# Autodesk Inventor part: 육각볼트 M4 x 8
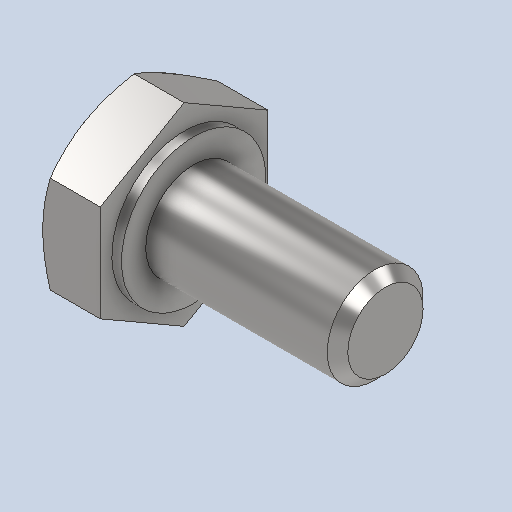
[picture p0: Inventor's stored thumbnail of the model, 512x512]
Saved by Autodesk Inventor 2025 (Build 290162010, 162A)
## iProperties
Created: 2024-07
Part Number: 육각볼트 M4 x 8
Material: 강철, 연강
Description: 6각 머리 나사
Document SubType Name: Modeling
Designer: Admin
Density: 7.86 g/cm^3
Appearance: 기본값
Author: jhkim
Sending System: Autodesk Inventor 2025
Preprocessor: ST-DEVELOPER v20
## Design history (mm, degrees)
feature "Solid1"
node "솔리드1"
